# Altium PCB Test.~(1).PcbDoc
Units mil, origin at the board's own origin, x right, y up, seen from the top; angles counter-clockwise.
Board outline 510.01 x 690.03 mil, 2 copper layers (Top Layer, Bottom Layer), stack 62 mil thick; 55 components, 19 nets, 99 pads, 0 vias.
Unrouted connection lines stored in the file: 68.
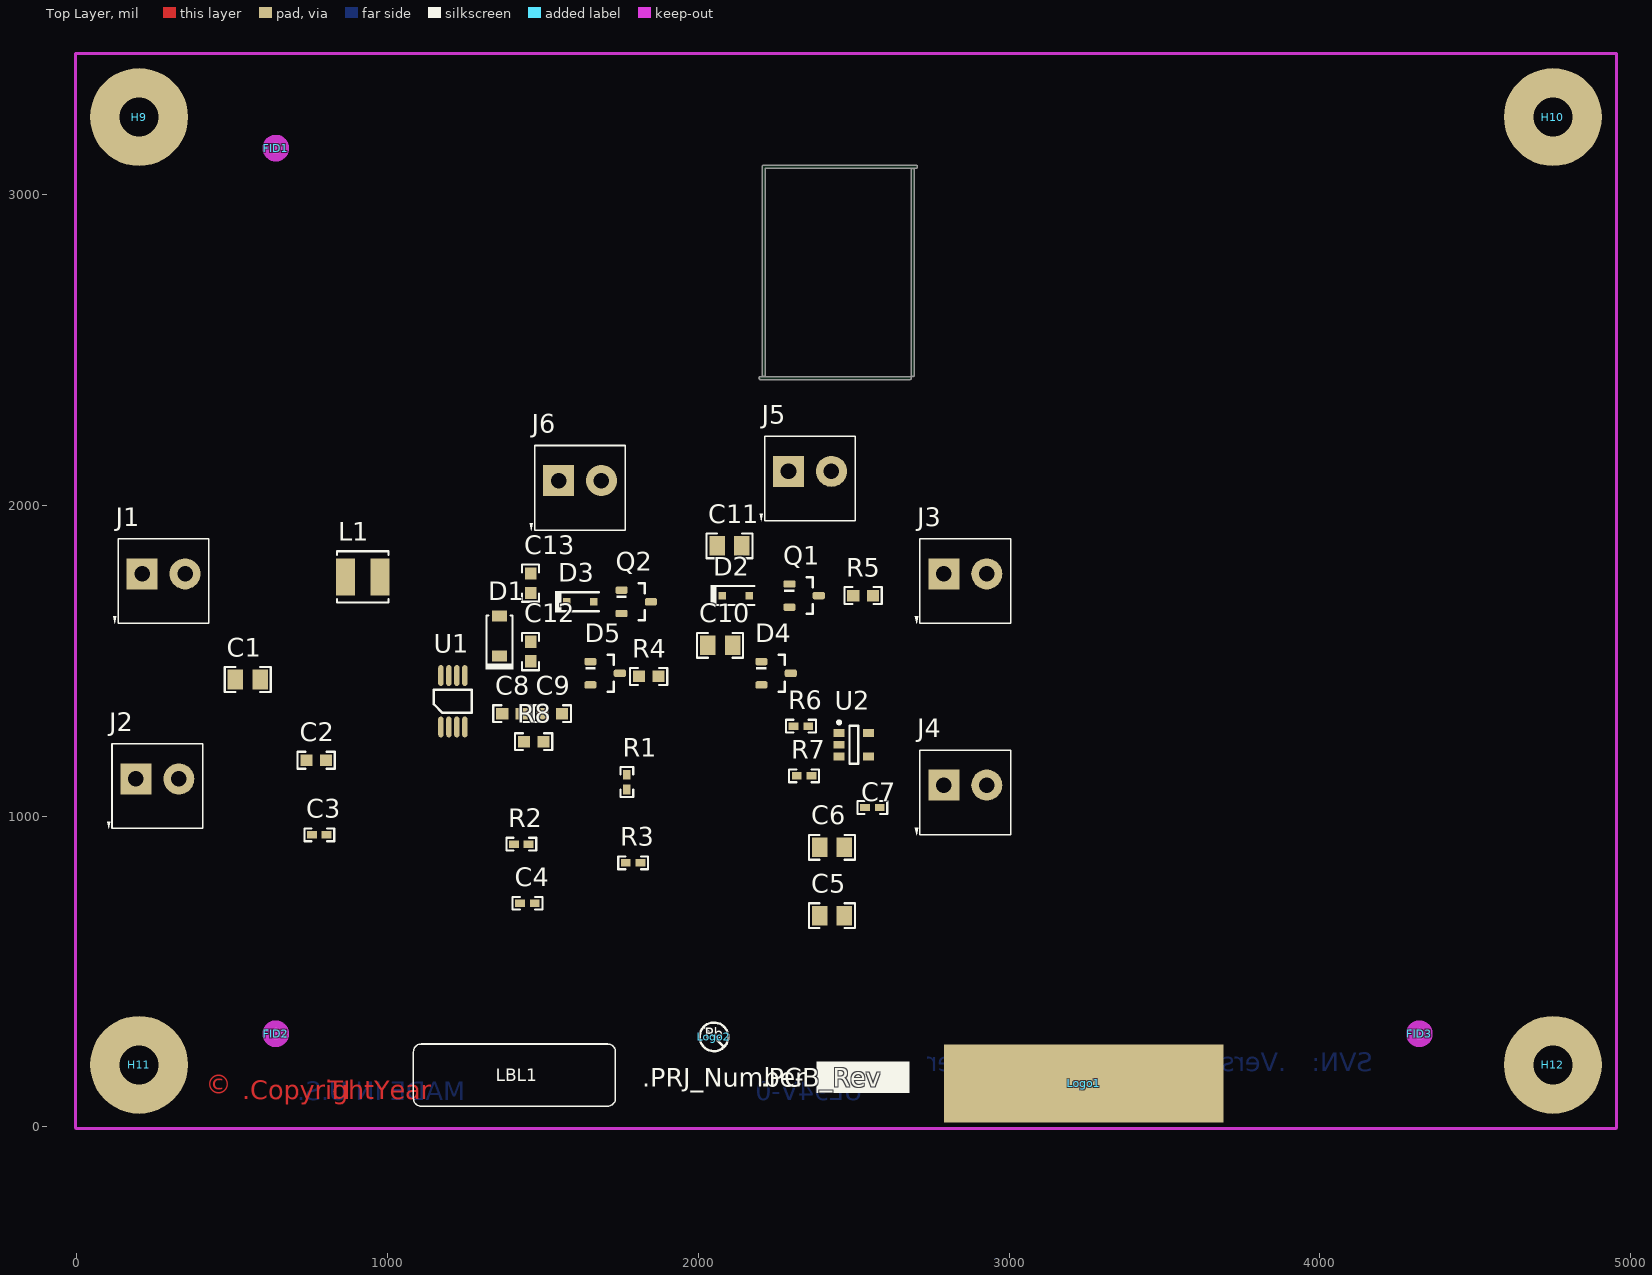
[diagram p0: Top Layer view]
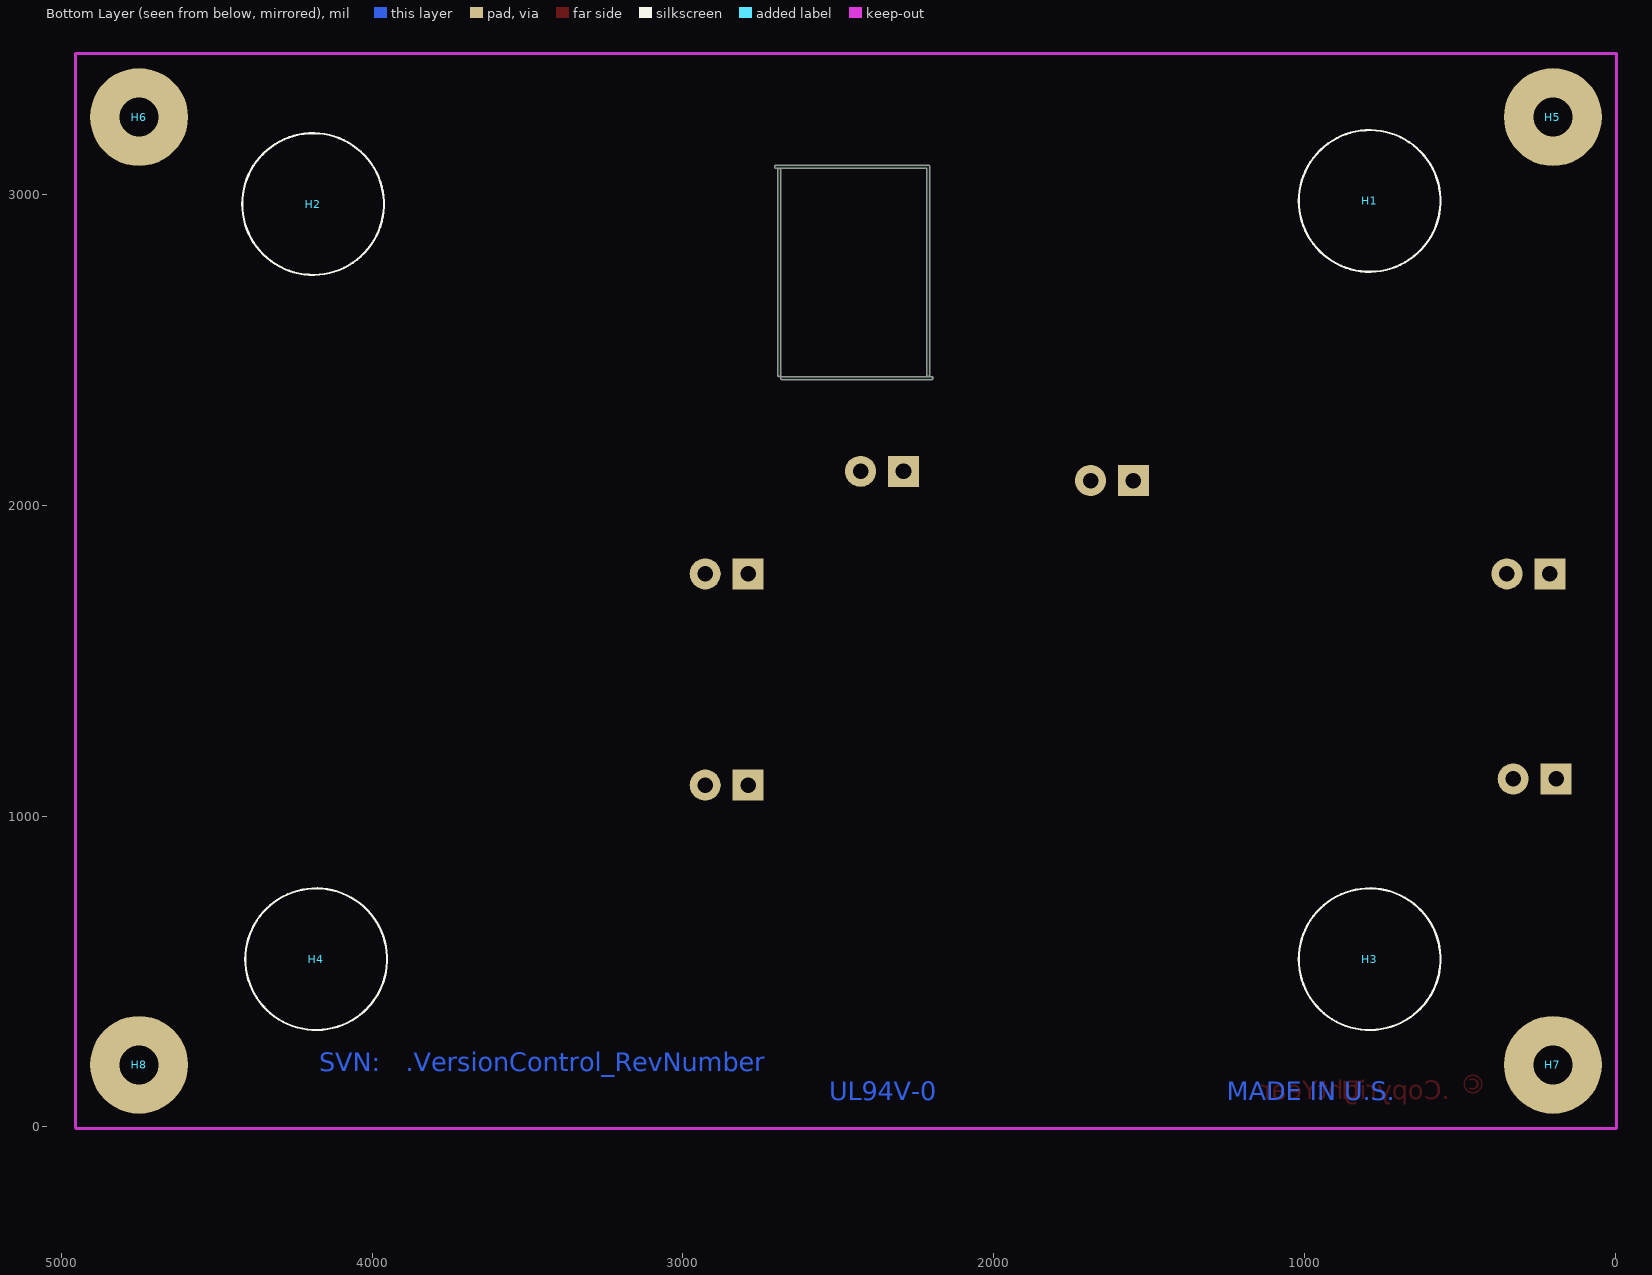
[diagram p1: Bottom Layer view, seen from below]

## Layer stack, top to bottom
Top Solder: solder mask 0.4, Solder Resist, Dk 3.5
Top Layer: signal copper 1.4
Dielectric1: core 59.2, FR-4, Dk 4.8
Bottom Layer: signal copper 1.4
Bottom Solder: solder mask 0.4, Solder Resist, Dk 3.5

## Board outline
2200,2404.99 cw(c2200,2410) 2200,2415.01 2209.45,2415.01 cw(c2210,2420) 2204.99,2420 2204.99,3090 cw(c2210,3090) 2210,3095.02 2700,3095.02 cw(c2700,3090) 2705.01,3090 cw(c2700,3090) 2700,3084.98 2690.55,3084.98 cw(c2690,3080) 2695.01,3080 2695.01,2420 cw(c2690,2420) 2684.99,2420 2684.99,3080 cw(c2690,3080) 2689.45,3084.98 2215.01,3084.98 2215.01,2420 cw(c2210,2420) 2210.55,2415.01 2680,2415.01 cw(c2680,2410) 2685.01,2410 cw(c2680,2410) 2680,2404.99

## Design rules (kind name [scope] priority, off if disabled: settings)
AcuteAngle [All] p1: minimum=4.50000000000000E+0001 checktracksonly=FALSE
AssemblyTestPointUsage [All] p1: valid=2
Clearance Clearance_Keepouts [((IsTrack Or IsArc) And Not InPoly) And IsFree and IsKeepOut vs ((IsTrack Or IsArc) And Not InPoly) And IsFree and IsKeepOut] p1: gap=0
Clearance Clearance_BoardEdge_MountingHoles [OnCopper and InComponentClass('Mounting Holes') vs IsKeepOut] p2: gap=40
Clearance Clearance_BoardEdge_Poly [OnCopper and InPoly vs IsKeepOut] p3: gap=25
Clearance Clearance_BoardEdge [OnCopper and Not InComponentClass('Logo') and not InComponentClass('FiducialMark') and not InRegion(1000,500,4000,800) and Not IsKeepout vs IsKeepOut] p4: gap=75
Clearance Clearance_Poly [InPolygon] p5: gap=25
Clearance [All] p6: gap=7.87
ComponentClearance ComponentClearance_MountingHoles_FiducialMarks [InComponentClass('Mounting Holes') vs InComponentClass('FiducialMark')] p1: gap=50 collisioncheckmode=3 verticalgap=10 showdistances=FALSE
ComponentClearance ComponentClearance_Shunt [InComponentClass('Header') vs InComponentClass('Shunt')] p2: gap=0 collisioncheckmode=3 verticalgap=0 showdistances=FALSE
ComponentClearance ComponentClearance_Logo [InComponentClass('Logo')] p3: gap=50 collisioncheckmode=3 verticalgap=10 showdistances=FALSE
ComponentClearance ComponentClearance_ScrewToNut [(HasFootprint('NY PMS 440 0025 PH')) vs (HasFootprint('Keystone_1902C'))] p4: gap=5 collisioncheckmode=3 verticalgap=10 showdistances=FALSE
ComponentClearance ComponentClearance_MountingHoles [InComponentClass('Mounting Holes')] p5: gap=250 collisioncheckmode=3 verticalgap=100000 showdistances=FALSE
ComponentClearance ComponentClearance_SmallPassives [HasFootprint('0201*') or HasFootprint('0402*') or HasFootprint('0508') or HasFootprint('0603*') or HasFootprint('0612') or HasFootprint('0805*') or HasFootprint('0815*') or HasFootprint('0830*') or HasFootprint('1206*') or HasFootprint('1210*') or HasFootprint('1808*') or HasFootprint('1812*') or HasFootprint('1825*') or HasFootprint('2010*') or HasFootprint('2220*') or HasFootprint('2225*') or HasFootprint('2512*') or HasFootprint('2728*') or HasFootprint('3518*') vs HasFootprint('0201*') or HasFootprint('0402*') or HasFootprint('0508') or HasFootprint('0603*') or HasFootprint('0612') or HasFootprint('0805*') or HasFootprint('0815*') or HasFootprint('0830*') or HasFootprint('1206*') or HasFootprint('1210*') or HasFootprint('1808*') or HasFootprint('1812*') or HasFootprint('1825*') or HasFootprint('2010*') or HasFootprint('2220*') or HasFootprint('2225*') or HasFootprint('2512*') or HasFootprint('2728*') or HasFootprint('3518*')] p6: gap=20 collisioncheckmode=3 verticalgap=10 showdistances=FALSE
ComponentClearance ComponentClearance_THtoSMT [IsThruComponent vs IsSMTComponent] p7: gap=100 collisioncheckmode=3 verticalgap=30 showdistances=FALSE
ComponentClearance ComponentClearance_THtoTH [IsThruComponent vs IsThruComponent] p8: gap=118.11 collisioncheckmode=3 verticalgap=30 showdistances=FALSE
ComponentClearance [All] p9: gap=40 collisioncheckmode=3 verticalgap=10 showdistances=FALSE
DiffPairsRouting [All] p1: maxlimit=100 minlimit=10 mostfreqgap=10 toplayer_minwidth=15 toplayer_maxwidth=15 toplayer_prefwidth=15 bottomlayer_minwidth=15 bottomlayer_maxwidth=15 bottomlayer_prefwidth=15 maxuncoupledlength=1000
FabricationTestPointUsage TestPointUsage [All] p1: valid=2 allowmultiple=FALSE
FabricationTestpoint Testpoint [All] p1: side=3 testpointundercomponent=TRUE minsize=40 maxsize=100 preferedsize=60 minholesize=0 maxholesize=40 preferedholesize=32 testpointgrid=1 allowsidetop=TRUE allowsidebottom=TRUE usegrid=TRUE gridtolerance=0.01
FanoutControl Fanout_LCC [IsLCC] p1: bgadir=Out bgaviamode=Centered fanoutstyle=Auto fanoutdirection=Alternating viagrid=1 // Fanout_LCC (Default Rule)
FanoutControl Fanout_BGA [IsBGA] p2: bgadir=Out bgaviamode=Centered fanoutstyle=Auto fanoutdirection=Alternating viagrid=1 // Fanout_BGA (Default Rule)
FanoutControl Fanout_Default [All] p4: bgadir=Out bgaviamode=Centered fanoutstyle=Auto fanoutdirection=Alternating viagrid=1 // Fanout_Default (Default Rule)
FanoutControl Fanout_Small [(CompPinCount < 5)] p5: bgadir=Out bgaviamode=Centered fanoutstyle=Auto fanoutdirection=OutThenIn viagrid=1 // Fanout_Small (Default Rule)
HoleSize [All] p1: absolutevalues=TRUE maxlimit=251 minlimit=8 maxpercent=80.000 minpercent=20.000
MinimumAnnularRing MinimumAnnularRing_ThermalPadVias [IsVia and InAnyComponent] p1: minimumring=5.91
MinimumAnnularRing [All] p2: minimumring=9
MinimumSolderMaskSliver MinimumSolderMaskSliver_Logo [InComponentClass('Logo') vs InComponentClass('Logo')] p1: minsoldermaskwidth=0.7
MinimumSolderMaskSliver [All] p2: minsoldermaskwidth=3.94
PlaneConnect [All] p1: planeconnectstyle=Relief reliefexpansion=10 reliefentries=4 reliefconductorwidth=10 reliefairgap=10
PolygonConnect [All] p1: connectstyle=Relief reliefconductorwidth=10 reliefentries=4 polygonreliefangle="90 Angle" airgapwidth=10
RoutingVias ThermalPadVias [IsVia and InAnyComponent] p1: holewidth=7.87 width=19.68 viastyle="Through Hole" minholewidth=7.87 minwidth=19.68 maxholewidth=12.99 maxwidth=23.62
RoutingVias [All] p2: holewidth=16 width=34 viastyle="Through Hole" minholewidth=7.87 minwidth=26 maxholewidth=40 maxwidth=65
SilkToBoardRegionClearance [Not ((IsComment or IsDesignator) And (Hide <> 'False')) and not InRegion(1000,500,4000,800)] p1:
SilkToSilkClearance SilkToSilkClearance_Pb-FreeLogo [(HasFootprint('Pb-Free_Overlay_Medium') OR HasFootprint('Pb-Free_Overlay_Small')) vs (HasFootprint('Pb-Free_Overlay_Medium') OR HasFootprint('Pb-Free_Overlay_Small'))] p1: silktosilkclearance=0
SilkToSilkClearance [All] p2: silktosilkclearance=5
SilkToSolderMaskClearance "Silk to Solder Mask Opening" [All] p1: minsilkscreentomaskgap=1 clearancetoexposedcopper=FALSE
SolderMaskExpansion [All] p1: expansion=1.97
UnpouredPolygon [All] p1: allowunpoured=FALSE
Width [All] p1: maxlimit=100 minlimit=6 preferedwidth=10 checkconnectedcopper=TRUE
14 further rules are at their usual default settings.

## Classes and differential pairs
component class Label: LBL1
component class FiducialMark: FID1 FID2 FID3
component class "TPS61085 reference board_Hardware": FID1 FID2 FID3 H1 H2 H3 H4 H5 H6 H7 H8 H9 H10 H11 H12 LBL1 Logo1 Logo2
component class Logo: Logo1
component class "Mounting Holes": H1 H4 H10 H11
component class "TPS61085 reference board": C1 C2 C3 C4 C5 C6 C7 C8 C9 C10 C11 C12 C13 D1 D2 D3 D4 D5 J1 J2 J3 J4 J5 J6 L1 Q1 Q2 R1 R2 R3 R4 R5 R6 R7 R8 U1 U2

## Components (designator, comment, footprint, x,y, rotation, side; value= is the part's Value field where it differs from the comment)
C1 "GRM219R61A106KE44D" 0805_HV 550,1440 r0 top
C2 "GRM185R61C105KE44D" 0603 770,1180 r0 top
C3 "GRM155R71C104KA88D" 0402 780,940 r0 top
C4 "GRM155R61C222KA01D" 0402 1450,720 r0 top
C5 "C2012X5R1E106K125AB" 0805_HV 2430,680 r0 top
C6 "C2012X5R1E106K125AB" 0805_HV 2430,900 r0 top
C7 "GRM155R71C104KA88D" 0402 2560,1028.19 r0 top
C8 "06035C104KAT2A" 0603 1400,1330 r0 top
C9 "06035C104KAT2A" 0603 1530,1330 r0 top
C10 "C2012X7R1H105K125AB" 0805_HV 2070,1550 r0 top
C11 "C2012X7R1H105K125AB" 0805_HV 2100,1870 r0 top
C12 "GRM185R61C105KE44D" 0603 1460,1530 r90 top
C13 "GRM185R61C105KE44D" 0603 1460,1750 r90 top
D1 "MBR120LSFT1G" SOD-123FL 1360,1580 r90 top
D2 "MMSZ5248BS-7-F" sod-323 2120,1710 r0 top
D3 "MMSZ5236BS-7-F" sod-323 1620,1690 r0 top
D4 "BAT54SLT1G" SOT-23 2250,1460 r0 top
D5 "BAT54SLT1G" SOT-23 1700,1460 r0 top
FID1 "Fiducial" Fiducial10-20 640,3150 r0 top
FID2 "Fiducial" Fiducial10-20 640,300 r0 top
FID3 "Fiducial" Fiducial10-20 4320,300 r0 top
H1 "SJ-5303 (CLEAR)" Bumpon_SJ5003Transparent 790,2980 r180 bottom
H2 "SJ-5303 (CLEAR)" Bumpon_SJ5003Transparent 4190,2970 r180 bottom
H3 "SJ-5303 (CLEAR)" Bumpon_SJ5003Transparent 790,540 r180 bottom
H4 "SJ-5303 (CLEAR)" Bumpon_SJ5003Transparent 4180,540 r180 bottom
H5 "1902C" Keystone_1902C 200,3250 r180 bottom locked
H6 "1902C" Keystone_1902C 4750,3250 r180 bottom locked
H7 "1902C" Keystone_1902C 200,200 r180 bottom locked
H8 "1902C" Keystone_1902C 4750,200 r180 bottom locked
H9 "NY PMS 440 0025 PH" "NY PMS 440 0025 PH" 200,3250 r0 top locked
H10 "NY PMS 440 0025 PH" "NY PMS 440 0025 PH" 4750,3250 r0 top locked
H11 "NY PMS 440 0025 PH" "NY PMS 440 0025 PH" 200,200 r0 top locked
H12 "NY PMS 440 0025 PH" "NY PMS 440 0025 PH" 4750,200 r0 top locked
J1 "ED555/2DS" TERM_BLK_ED555-2DS 210,1780 r0 top
J2 "ED555/2DS" TERM_BLK_ED555-2DS 190,1120 r0 top
J3 "ED555/2DS" TERM_BLK_ED555-2DS 2790,1780 r0 top
J4 "ED555/2DS" TERM_BLK_ED555-2DS 2790,1100 r0 top
J5 "ED555/2DS" TERM_BLK_ED555-2DS 2290,2110 r0 top
J6 "ED555/2DS" TERM_BLK_ED555-2DS 1550,2080 r0 top
L1 "LQH44PN3R3MP0L" IND_LQH44P 920,1770 r0 top
LBL1 "Size: 0.65\" x 0.20 \"" Label_650x200 1408,167 r0 top
Logo1 "Texas Instruments" TI_Stacked_SolderMask_Small 3240,140 r0 top
Logo2 "Pb-Free Symbol" Pb-Free_Overlay_Small 2050,290 r0 top
Q1 "BC850CLT1G" SOT-23 2340,1710 r0 top
Q2 "BC857C-7-F" SOT-23 1800,1690 r0 top
R1 "CRCW040216K0JNED" 0402 1770,1110 r90 top
R2 "CRCW040227K0JNED" 0402 1430,910 r0 top
R3 "CRCW0402113KFKED" 0402 1790,850 r0 top
R4 "CPF0603B2K0E" 0603 1840,1450 r0 top
R5 "CPF0603B2K0E" 0603 2530,1710 r0 top
R6 "CRCW040227K0JNED" 0402 2330,1290 r0 top
R7 "CRCW040227K0JNED" 0402 2340,1130 r0 top
R8 "CRCW060310R0FKEA" 0603 1470,1240 r0 top
U1 "TPS61085DGKR" DGK0008A_N 1210,1370 r90 top
U2 "LM7321MF" MF05A_L 2500,1230 r0 top

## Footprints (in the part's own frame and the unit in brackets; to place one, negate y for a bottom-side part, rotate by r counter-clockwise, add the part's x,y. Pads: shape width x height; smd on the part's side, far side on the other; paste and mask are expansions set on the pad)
0402 [mm] "0402 from SM-752 data"
  rect 0.8x0.6 smd: 1(-0.6,0) 2(0.6,0)
  silkscreen extent -1.22,-0.52 1.22,0.52, body extent -0.55,-0.3 0.55,0.3, height 0.6
0603 [mm] "0603 from SM-752 data"
  rect 1x0.95 smd: 1(-0.8,0) 2(0.8,0)
  silkscreen extent -1.52,-0.69 1.52,0.69, body extent -0.87,-0.47 0.87,0.47, height 0.85
0805_HV [mil] "0805 with 30mil clearance between pads"
  rect 50x63 smd: 1(-40,0) 2(40,0)
  silkscreen extent -74,-40 74,40, body extent -43,-29 43,29, height 43
Bumpon_SJ5003Transparent [mil] "3M Hemispherical Bumpon transparent"
  round 1 on Mech4: 0(0,0)
  silkscreen extent -228,-228 228,228, body extent -217,-218 219,218, height 197
DGK0008A_N [mm] "TSOP, 8-Leads, Body 3x3mm, Pitch 0.65mm, IPC Medium Density"
  oval 1.7x0.45 smd mask+0.05: 1(-2.1,0.975) 2(-2.1,0.325) 3(-2.1,-0.325) 4(-2.1,-0.975) 5(2.1,-0.975) 6(2.1,-0.325) 7(2.1,0.325) 8(2.1,0.975)
  silkscreen extent -0.95,-1.55 0.95,1.55, body extent -2.45,-1.5 2.45,1.5, height 0.94
Fiducial10-20 [mm]
  round 1 smd mask+0.5: 1(0,0)
  Top Layer keep-out circle w1.178: c0,0 r0.5
IND_LQH44P [mm] "Murata"
  rect 1.55x3 smd: 1(-1.425,0) 2(1.425,0)
  silkscreen extent -2.1,-2.1 2.1,2.1, body extent -2.1,-2.1 2.1,2.1, height 1.8
Keystone_1902C [mil] "Hex Standoff, 4-40 threaded, nylon"
  body extent -145,-126 146,126, height 501
Label_650x200 [mil] "Thermal Transfer Label"
  silkscreen extent -325,-100 325,100, body extent -326,-101 326,101, height 1
MF05A_L [mm] "SOT23, 5-Leads, Body 2.9x1.6mm, Pitch 0.95mm, Lead Span 2.8mm, IPC High Density"
  rect 0.9x0.65 smd: 1(-1.2,0.95) 2(-1.2,0) 3(-1.2,-0.95) 4(1.2,-0.95) 5(1.2,0.95)
  silkscreen extent -1.32,-1.55 0.35,1.95, body extent -0.9,-1.55 0.9,1.55, height 1.19
"NY PMS 440 0025 PH" [mm] "4-40 nylon screw and mounting hole"
  round 8 hole 3.2: 1(0,0)
  body extent -3.3,-3.3 3.3,3.3, height 2.69
Pb-Free_Overlay_Small [mil]
  silkscreen extent -46,-46 46,46
SOD-123FL [mm] "Copied from SOD-123"
  rect 0.915x1.22 smd: 1(-1.637,0) 2(1.637,0)
  silkscreen extent -2.74,-1.16 1.68,1.16, body extent -1.9,-0.9 1.9,0.9, height 1
sod-323 [mm] "NXP recommended land pattern"
  rect 0.6x0.6 smd paste-0.05: 1(-1.1,0) 2(1.1,0)
  silkscreen extent -2.06,-0.86 1.53,0.86, body extent -1.3,-0.67 1.3,0.68, height 1.1
SOT-23 [mm] "SOT23, 3-Leads, Body 2.9x1.3mm, Pitch 0.95mm, Lead Span 2.5mm, IPC Medium Density"
  rrect50% 1x0.6 smd: 1(-1.2,0.95) 2(-1.2,-0.95) 3(1.2,0)
  silkscreen extent -1.63,-1.5 0.7,1.5, body extent -1.16,-1.45 1.21,1.45, height 1
TERM_BLK_ED555-2DS [mil]
  rect 100x100 hole 50: 1(0,0)
  round 100 hole 50: 2(138,0)
  silkscreen extent -93,-161 215,113, body extent -69,-150 207,106, height 323
TI_Stacked_SolderMask_Small [mil]
  rect 900x250 smd paste-125 mask-125: 0(0,0)

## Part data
C1: "CAP, CERM, 10 μF, 10 V, +/- 10%, X5R, 0805"
C2 C12 C13: "CAP, CERM, 1 μF, 16 V, +/- 10%, X5R, 0603"
C3 C7: "CAP, CERM, 0.1 μF, 16 V, +/- 10%, X7R, 0402"
C4: "CAP, CERM, 2200 pF, 16 V, +/- 10%, X5R, 0402"
C5 C6: "CAP, CERM, 10 μF, 25 V, +/- 10%, X5R, 0805"
C8 C9: "CAP, CERM, 0.1 μF, 50 V, +/- 10%, X7R, 0603"
C10 C11: "CAP, CERM, 1 μF, 50 V, +/- 10%, X7R, 0805"
D1: "Diode, Schottky, 20 V, 1 A, SOD-123FL"
D2: "Diode, Zener, 18 V, 200 mW, SOD-323"
D3: "Diode, Zener, 7.5 V, 200 mW, SOD-323"
D4 D5: "Diode, Schottky, 30 V, 0.2 A, SOT-23"
FID1 FID2 FID3: "Fiducial mark.  There is nothing to buy or mount."
H1 H2 H3 H4: "Bumpon, Hemisphere, 0.44 X 0.20, Clear"
H5 H6 H7 H8: "Standoff, Hex, 0.5\"L #4-40 Nylon"
H9 H10 H11 H12: "Machine Screw, Round, #4-40 x 1/4, Nylon, Philips panhead"
J1 J2 J3 J4 J5 J6: "Terminal Block, 6A, 3.5mm Pitch, 2-Pos, TH"
L1: "Inductor, Shielded Drum Core, Ferrite, 3.3 μH, 1.77 A, 0.065 ohm, SMD"
LBL1: library part THT-14-423-10, "Thermal Transfer Printable Labels, 0.650\" W x 0.200\" H - 10,000 per roll"
Logo1: library part TI_Logo, "Texas Instrument Corporate Signature"
Logo2: library part Pb-Free
Q1: library part "BC850CLT1G, ON Semiconductor", "Transistor, NPN, 45 V, 0.1 A, SOT-23"
Q2: library part "BC857C-7-F, Diodes Inc.", "Transistor, PNP, 45 V, 0.1 A, SOT-23"
R1: "RES, 16 k, 5%, 0.063 W, 0402"
R2 R6 R7: "RES, 27 k, 5%, 0.063 W, 0402"
R3: "RES, 113 k, 1%, 0.063 W, 0402"
R4 R5: "RES, 2.00 k, 0.1%, 0.063 W, 0603"
R8: "RES, 10.0, 1%, 0.1 W, 0603"
U1: "18.5 V, 2 A, 650 KHz / 1.2 MHz Step-Up DC-DC Converter with Forced PWM Mode, 2.3 to 6 V, -40 to 85 degC, 8-pin SOP (DGK8), Green (RoHS & no Sb/Br)"
U2: "Single 30V High Output Current and Unlimited Capacitive Load Op Amp"

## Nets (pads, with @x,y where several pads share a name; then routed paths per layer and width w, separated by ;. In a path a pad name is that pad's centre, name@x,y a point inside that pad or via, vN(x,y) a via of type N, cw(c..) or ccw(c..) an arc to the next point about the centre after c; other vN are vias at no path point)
NetC1_1: C1.1 C2.1 J1.1 J1.2 L1.1 U1.3 U1.6 U1.7
NetC3_1: C3.1 U1.8
NetC4_1: C4.1 R2.1
NetC5_1: C5.1 C6.1 D1.1 D4.1 J3.1 R3.2 R7.2 U2.2
NetC7_1: C7.1 J4.1 U2.1 U2.4
NetC8_1: C8.1 C9.2 R8.2
NetC8_2: C8.2 D5.3
NetC9_1: C9.1 D4.3
NetC10_1: C10.1 D4.2 Q1.3 R5.2
NetC11_1: C11.1 J5.1 Q1.2
NetC12_1: C12.1 D5.1 Q2.3 R4.2
NetC13_1: C13.1 J6.1 Q2.2
NetD1_2: D1.2 L1.2 R8.1 U1.5
NetD2_1: D2.1 Q1.1 R5.1
NetD3_2: D3.2 Q2.1 R4.1
NetR1_2: R1.2 R3.1 U1.2
NetR2_2: R2.2 U1.1
NetR6_2: R6.2 R7.1 U2.3
PGND: C1.2 C2.2 C3.2 C4.2 C5.2 C6.2 C7.2 C10.2 C11.2 C12.2 C13.2 D2.2 D3.1 D5.2 J2.1 J2.2 J3.2 J4.2 J5.2 J6.2 R1.1 R6.1 U1.4 U2.5
pads on no net: FID1.1 FID2.1 FID3.1 H1.0 H2.0 H3.0 H4.0 H9.1 H10.1 H11.1 H12.1 Logo1.0

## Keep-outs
Keep-Out Layer:
  lines w10: -5,0 ccw(c0,0) 0,-5 ; -5,0 ccw(c0,0) 0,-5 ; -5,0 -5,3450 ; -5,3450 cw(c0,3450) 0,3455 ; -5,3450 cw(c0,3450) 0,3455 ; 0,-5 4950,-5 ; 0,3455 4950,3455 ; 4950,-5 ccw(c4950,0) 4955,0 ; 4950,-5 ccw(c4950,0) 4955,0 ; 4950,3455 cw(c4950,3450) 4955,3450 ; 4950,3455 cw(c4950,3450) 4955,3450 ; 4955,0 4955,3450
  text ".Layer_Name" at 577,-858.49 h60

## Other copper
Top Layer:
  text ".CopyrightYear" at 532,90 h60
  text "TI" at 808,90 h60
  text "©" at 415,86.48 h105
  text ".Layer_Name" at 577,-858.49 h60
Bottom Layer:
  text ".VersionControl_RevNumber" at 3891,179.5 h60
  text "SVN:" at 4170,179.5 h60
  text "MADE IN U.S." at 1250,86.5 h60
  text "UL94V-0" at 2529.5,86.5 h60
  text ".Layer_Name" at 577,-858.49 h60

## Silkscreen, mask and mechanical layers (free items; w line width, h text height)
Top Overlay:
  region: 2680,210 2380,210 2380,110 2680,110
  text ".PRJ_Number" at 1820,130.01 h60
  text ".PCB_Rev" at 2200,130.01 h60
  text "-" at 2310,130.01 h60
  text ".Layer_Name" at 577,-858.49 h60
Bottom Overlay:
  text ".Layer_Name" at 577,-858.49 h60
Top Paste:
  text ".Layer_Name" at 577,-858.49 h60
Bottom Paste:
  text ".Layer_Name" at 577,-858.49 h60
Top Solder:
  text ".Layer_Name" at 577,-858.49 h60
  text ".Layer_Name" at 577,-858.49 h60
Bottom Solder:
  text ".Layer_Name" at 577,-858.49 h60
Drill Guide:
  text ".Layer_Name" at 577,-858.49 h60
M1 Board Outline:
  lines w10: 0,0 4950,0 4950,3450 0,3450 0,0 ; 2200,2410 2210,2420 2210,3090 2700,3090 2690,3080 2690,2420 2680,2410 2200,2410
  text ".Layer_Name" at 577,-858.49 h60
M2 Board Dimensions:
  rectangle: 125,-400 500,-275
  rectangle: 0,-275 125,-150
  lines w7: 0,-275 1000,-275 ; 125,-400 125,-150 ; 250,-400 250,-150 ; 500,-400 500,-150 ; 750,-400 750,-150 ; 0,-400 0,-150 1000,-150 1000,-400 0,-400
  text ".Layer_Name" at 577,-858.49 h60
M3 3D STEP Top:
  text ".Layer_Name" at 577,-858.49 h60
M4 3D STEP Bottom:
  text ".Layer_Name" at 577,-858.49 h60
M5 Assembly Top:
  lines w10: -292,-930.17 6308,-930.17 ; -292,-726.83 6310,-726.83 ; -292,-523.5 -292,-1133.5 3713,-1133.5 6310,-1133.5 6310,-523.5 -291.5,-523.5 -291.5,-1133.5 1284,-1133.5 ; 2173,-1133.5 2173,-523.5 ; 3440,-726.83 3440,-523.5 ; 4280,-726.83 4280,-523.5 ; 4902,-1140 4902,-937.17
  text "COMPONENTS MARKED 'DNP' SHOULD NOT BE POPULATED." at 1153.5,-318.5 h60
  text "ASSEMBLY VARIANT:" at 1153,-434 h60
  text ".VariantName" at 2189,-434 h60
  text "PCB VIEWED FROM TOP SIDE" at -228.5,-655.67 h60
  text "BOARD #:" at 2248,-655.67 h60
  text ".PRJ_Number" at 2793.5,-655.67 h60
  text "REV:" at 3638,-655.67 h60
  text ".PCB_Rev" at 3929.5,-655.67 h60
  text "SVN REV:" at 4476,-655.67 h60
  text ".VersionControl_RevNumber" at 4982,-655.67 h60
  text "PLOT NAME =" at -228.5,-1064.34 h60
  text ".plot_File_Name" at 577,-1064.34 h60
  text "GENERATED    :" at 2250,-1064.34 h60
  text ".Print_Date" at 3119.5,-1064.34 h60
  text ".Print_Time" at 3848.5,-1064.34 h60
  text "TEXAS INSTRUMENTS" at 5113,-1064.34 h60
M6 Assembly Bottom:
  lines w10: -292.5,-727.33 6309.5,-727.33 ; -290.5,-930.67 6309.5,-930.67 ; 1115.5,-1140.5 1115.5,-937.67 ; 1737.5,-727.33 1737.5,-524 ; 2577.5,-727.33 2577.5,-524 ; 3844.5,-1134 3844.5,-524 ; 4733.5,-1134 6309,-1134 6309,-524 -292.5,-524 -292.5,-1134 2304.5,-1134 6309.5,-1134 6309.5,-524
  text "COMPONENTS MARKED 'DNP' SHOULD NOT BE POPULATED." at 6102,-318 h60
  text ".VariantName" at 5058,-434 h60
  text "ASSEMBLY VARIANT:" at 6097,-434 h60
  text ".VersionControl_RevNumber" at 1035.5,-656.17 h60
  text "SVN REV:" at 1541.5,-656.17 h60
  text ".PCB_Rev" at 2088,-656.17 h60
  text "REV:" at 2379.5,-656.17 h60
  text ".PRJ_Number" at 3224,-656.17 h60
  text "BOARD #:" at 3769.5,-656.17 h60
  text "PCB VIEWED FROM BOTTOM SIDE" at 6246,-656.17 h60
  text "TEXAS INSTRUMENTS" at 904.5,-1064.84 h60
  text ".Print_Time" at 2169,-1064.84 h60
  text ".Print_Date" at 2898,-1064.84 h60
  text "GENERATED    :" at 3767.5,-1064.84 h60
  text ".plot_File_Name" at 5440.5,-1064.84 h60
  text "PLOT NAME =" at 6246,-1064.84 h60
M9 Title Sheet:
  drawing of 57 lines, arcs and shapes, not listed
  text "1" at 739.84,8036.5 h70
  text "2" at 3235.5,8036.5 h70
  text "3" at 5724.84,8036.5 h70
  text "4" at 8231.51,8036.5 h70
  text "5" at 10730.5,8036.5 h70
  text "6" at 13235.5,8036.5 h70
  text "A" at -416.5,6893.5 h70
  text "A" at 14383.5,6893.5 h70
  text "B" at -416.5,4513.5 h70
  text "B" at 14383.5,4513.5 h70
  text "C" at -416.5,2138.5 h70
  text "C" at 14383.5,2138.5 h70
  text "PROJECT TITLE:" at 11343.5,277.5 h45
  text ".PRJ_Title" at 11393.5,144.17 h70
  text "DESIGNED FOR:" at 11343.5,-23.5 h45
  text ".PRJ_Customer" at 11393.5,-163.5 h70
  text "D" at -416.5,-231.5 h70
  text "D" at 14383.5,-231.5 h70
  text "FILE NAME:" at 11343.5,-323.5 h45
  text ".PCB_File_Name_No_Path" at 11393.5,-443.5 h70
  text "Texas Instruments (TI) and/or its licensors do not warrant the accuracy or completeness of this specification" at 6374,-605.34 h45
  text "ENGINEER:" at 11343.5,-613.5 h45
  text "LAYOUT BY:" at 12848.5,-613.5 h45
  text "or any information contained therein. TI and/or its licensors do not warrant that this design will meet" at 6329.01,-718 h45
  text ".PRJ_Engineer" at 11393.5,-768.49 h70
  text ".PCB_Layout" at 12899,-768.49 h70
  text "the specifications, will be suitable for your application or fit for any particular purpose, or will operate in" at 6329.01,-830.67 h45
  text ".Layer_Name" at 577,-858.49 h60
  text "ALTIUM DESIGNER VERSION:" at 12848.5,-923.5 h45
  text "an implementation. TI and/or its licensors do not warrant that the design is production worthy. You should" at 6329.01,-943.33 h45
  text "completely validate and test your design implementation to confirm the system functionality for your application." at 6374,-1056 h45
  text ".print_Scale" at 11393.5,-1056.83 h70
  text ".Application_BuildNumber" at 12899,-1056.83 h70
  text "1" at 739.84,-1263.5 h70
  text "2" at 3235.5,-1263.5 h70
  text "3" at 5724.84,-1263.5 h70
  text "4" at 8231.51,-1263.5 h70
  text "5" at 10730.5,-1263.5 h70
  text "6" at 13235.5,-1263.5 h70
M10 Fab Notes:
  drawing of 185 lines, arcs and shapes, not listed
  text "DESIGN INFORMATION" at 12381.02,5910 h60
  text "MIN. TRACK WIDTH:" at 11736.46,5730 h60
  text "8" at 12832.7,5730 h60
  text "MIL" at 12987.46,5730 h60
  text "MIN. CLEARANCE:" at 11736.46,5598 h60
  text "0.2" at 12772.7,5598 h60
  text "mm" at 12987.46,5598 h60
  text "MIN. VIA PAD SIZE:" at 11736.46,5466 h60
  text "24" at 12802.71,5466 h60
  text "MIL" at 12987.46,5466 h60
  text "0.05mm (2MIL)" at 12431.46,5324.29 h60
  text "MINIMUM ANNULAR RING" at 11407.23,5320 h60
  text "EXTERNAL" at 13139.46,5320 h60
  text "PER" at 11607.23,5202 h60
  text "IPC-D-275 CLASS 2 LEVEL C" at 11827.23,5202 h60
  text "MIL, HOLES" at 13315.46,5089.71 h60
  text "+/-" at 12923,5089 h60
  text "+/-" at 13777,5089 h60
  text "REGISTRATION TOLERANCES:" at 11407.23,5084 h60
  text "METAL" at 12607,5084 h60
  text "5" at 13183.2,5084 h60
  text "3" at 14016.2,5084 h60
  text "MIL" at 14132.46,5084 h60
  text "MATERIAL:" at 11332.46,4874.54 h60
  text "FR-4 High Tg" at 12318.9,4734.21 h60
  text "FR-408" at 11753.46,4725.64 h60
  text "X" at 12165.46,4725.64 h60
  text "OTHER" at 13241.46,4725.64 h60
  text "62 MIL (1.6mm) +/-10%" at 12073.56,4562.92 h60
  text "THICKNESS:" at 11407.23,4558.64 h60
  text "X" at 11945.4,4558.64 h60
  text "OTHER" at 13358.46,4558.64 h60
  text "TOLERANCE:" at 11407.23,4400.64 h60
  text "X" at 12246.53,4400.64 h60
  text "ANSI IPC-6012 TYPE 3 CLASS 2" at 12433.48,4400.64 h60
  text "OTHER +/-" at 12433.46,4244.64 h60
  text "BOW & TWIST:" at 11407.23,4087.64 h60
  text "X" at 12246.53,4087.64 h60
  text "ANSI IPC-6012 TYPE 3 CLASS 2" at 12433.48,4087.64 h60
  text "OTHER +/-" at 12433.46,3929.13 h60
  text "DRILLING:" at 11332.46,3790.64 h60
  text "REFERENCE:" at 11407.23,3673.64 h60
  text "X" at 12055.46,3673.64 h60
  text "AS SHOWN" at 12242.46,3673.64 h60
  text "X" at 12956.46,3673.64 h60
  text "NC_DRILL FILES" at 13093.46,3673.64 h60
  text "PTH MIN COPPER THICKNESS:" at 11407.23,3515.64 h60
  text "X" at 12757.46,3515.64 h60
  text "1MIL" at 12894.46,3515.64 h60
  text "OTHER" at 13391.46,3515.64 h60
  text "BOARD FINISH:" at 11332.46,3356.64 h60
  text "SILKSCREEN:" at 11487.68,3238.64 h60
  text "X" at 12436.46,3238.64 h60
  text "TOP" at 12562.46,3238.64 h60
  text "X" at 12946.46,3238.64 h60
  text "BOTTOM" at 13073.46,3238.64 h60
  text "SILKSCREEN COLOR:" at 11487.68,3071.64 h60
  text "X" at 12435.42,3071.64 h60
  text "WHITE" at 12562.46,3071.64 h60
  text "OTHER" at 13073.46,3071.64 h60
  text "SOLDER RESIST COLOR:" at 11487.68,2901.64 h60
  text "X" at 12055.42,2742.44 h60
  text "GREEN" at 12182.46,2742.44 h60
  text "BLUE" at 12773.46,2742.44 h60
  text "OTHER" at 13311.46,2742.44 h60
  text "IMMERSION GOLD (ENIG)" at 12393.46,2553.92 h60
  text "ENEPIG" at 13731,2550.64 h60
  text "SURFACE FINISH:" at 11332.46,2549.64 h60
  text "X" at 12206.51,2549.64 h60
  text "IMM. TIN/SILVER OR EQUIV" at 11662,2392.64 h60
  text "OTHER" at 13093.46,2392.64 h60
  text "ARRAY/PANEL:" at 11332.46,2213.64 h60
  text "CUT AND TRIM PER MECH LAYER 1" at 12393.46,2209.35 h60
  text "N.C. ROUTE" at 12393.46,2057.64 h60
  text "X" at 13072.46,2057.64 h60
  text "V. SCORE" at 13259.46,2057.64 h60
  text "CERTIFICATION:" at 11332.46,1920.64 h60
  text "MATERIALS AND WORKMANSHIP FOR ALL PCBS" at 12057.46,1920.64 h60
  text "TO MEET OR EXCEED THE REQUIREMENTS OF:" at 12057.46,1822.64 h60
  text "X" at 11683.96,1686.13 h60
  text "ANSI IPC-A-600F CLASS ->" at 11822.96,1686.13 h60
  text "X" at 13462.02,1686.13 h60
  text "2" at 13580.96,1686.14 h60
  text "1" at 13265.96,1684.64 h60
  text "3" at 13934.96,1684.64 h60
  text "X" at 11686.02,1526.64 h60
  text "UL 94V-0" at 11822.96,1526.64 h60
  text "X" at 12498.02,1526.64 h60
  text "RoHS" at 12634.96,1526.64 h60
  text "OTHER" at 13279.36,1526.64 h60
  text "PER ORDER" at 13676.42,1526.64 h60
  text "ADDITIONAL REQUIREMENTS:" at 11332.46,1385.64 h60
  text "MICROSECTION:" at 11407.23,1270.64 h60
  text "YES" at 12312.96,1270.64 h60
  text "REQUIRED" at 13174.46,1114.49 h60
  text "BARE BOARD ELEC. TEST:" at 11407.23,1111.64 h60
  text "NONE" at 12712.96,1111.64 h60
  text "X" at 13047.46,1111.64 h60
  text "PER ORDER" at 13766.46,1111.64 h60
  text "MANUFACTURER'S UL:" at 11407.23,954.64 h60
  text "RAIL" at 12572.96,950.35 h60
  text "METAL" at 13064.77,950.35 h60
  text "X" at 13440,950 h60
  text "SILK" at 13576.46,950.35 h60
  text ".Layer_Name" at 577,-858.49 h60
M11 Gerber Information:
  lines w10: -292,-930.17 6308,-930.17 ; -292,-726.83 6310,-726.83 ; -292,-523.5 -292,-1133.5 3713,-1133.5 6310,-1133.5 6310,-523.5 -291.5,-523.5 -291.5,-1133.5 1284,-1133.5 ; 2173,-1133.5 2173,-523.5 ; 3440,-726.83 3440,-523.5 ; 4280,-726.83 4280,-523.5 ; 4902,-1140 4902,-937.17
  text "ALL ARTWORK VIEWED FROM TOP SIDE" at -228.5,-655.67 h60
  text "BOARD #:" at 2248,-655.67 h60
  text ".PRJ_Number" at 2793.5,-655.67 h60
  text "REV:" at 3638,-655.67 h60
  text ".PCB_Rev" at 3929.5,-655.67 h60
  text "SVN REV:" at 4476,-655.67 h60
  text ".VersionControl_RevNumber" at 4982,-655.67 h60
  text "LAYER NAME =" at -228.5,-858.49 h60
  text "PLOT NAME =" at -228.5,-1064.34 h60
  text ".plot_File_Name" at 577,-1064.34 h60
  text "GENERATED    :" at 2250,-1064.34 h60
  text ".Print_Date" at 3119.5,-1064.34 h60
  text ".Print_Time" at 3848.5,-1064.34 h60
  text "TEXAS INSTRUMENTS" at 5113,-1064.34 h60
M12 Stackup:
  drawing of 191 lines, arcs and shapes, not listed
  text "Layer" at 9790.34,7830 h60
  text "Name" at 10200.26,7830 h60
  text "Material" at 11130,7830 h60
  text "Thickness" at 11989.77,7830 h60
  text "Constant" at 12639.6,7830 h60
  text "Board Layer Stack" at 13209.46,7830 h60
  text "1" at 9790.34,7710 h60
  text "Top Overlay" at 10200.26,7710 h60
  text "2" at 9790.34,7590 h60
  text "Top Solder" at 10200.26,7590 h60
  text "Solder Resist" at 11130,7590 h60
  text "0.40mil" at 11989.77,7590 h60
  text "3.5" at 12639.6,7590 h60
  text "3" at 9790.34,7470 h60
  text "Top Layer" at 10200.26,7470 h60
  text "Copper" at 11130,7470 h60
  text "1.40mil" at 11989.77,7470 h60
  text "4" at 9790.34,7350 h60
  text "Dielectric1" at 10200.26,7350 h60
  text "FR-4" at 11130,7350 h60
  text "59.20mil" at 11989.77,7350 h60
  text "4.8" at 12639.6,7350 h60
  text "5" at 9790.34,7230 h60
  text "Bottom Layer" at 10200.26,7230 h60
  text "Copper" at 11130,7230 h60
  text "1.40mil" at 11989.77,7230 h60
  text "6" at 9790.34,7110 h60
  text "Bottom Solder" at 10200.26,7110 h60
  text "Solder Resist" at 11130,7110 h60
  text "0.40mil" at 11989.77,7110 h60
  text "3.5" at 12639.6,7110 h60
  text "7" at 9790.34,6990 h60
  text "Bottom Overlay" at 10200.26,6990 h60
  text ".Layer_Name" at 577,-858.49 h60
M13 Component Bodies Top:
  text ".Layer_Name" at 577,-858.49 h60
M14 Component Bodies Bottom:
  text ".Layer_Name" at 577,-858.49 h60
M15 Courtyards Top:
  text ".Layer_Name" at 577,-858.49 h60
M16 Courtyards Bottom:
  text ".Layer_Name" at 577,-858.49 h60
Drill Drawing:
  circle w1: c5692.72,3221.04 r24.89
  lines w1: 5667.83,3046.84 5717.6,3046.84 5717.6,3096.61 5667.83,3096.61 5667.83,3046.84
  lines w12: 5600,3002.04 7718.02,3002.04 ; 5600,3300.68 7718.02,3300.68 ; 5970.36,2852.72 5970.36,3450 ; 6327.36,2852.72 6327.36,3450 ; 6988.93,2852.72 6988.93,3450 ; 7273.07,2852.72 7273.07,3450 ; 5600,2852.72 7718.02,2852.72 7718.02,3450 5600,3450 5600,2852.72
  text "Symbol" at 5689.59,3345.48 h72
  text "Quantity" at 6015.16,3345.48 h72
  text "Finished Hole Size" at 6372.16,3345.48 h72
  text "Plated" at 7033.72,3345.48 h72
  text "Hole Type" at 7317.86,3345.48 h72
  text "12" at 6015.16,3196.16 h60
  text "50.00mil (1.270mm)" at 6372.16,3196.16 h60
  text "PTH" at 7033.72,3196.16 h60
  text "Round" at 7317.86,3196.16 h60
  text "4" at 6015.16,3046.84 h60
  text "125.98mil (3.200mm)" at 6372.16,3046.84 h60
  text "PTH" at 7033.72,3046.84 h60
  text "Round" at 7317.86,3046.84 h60
  text "16 Total" at 6015.16,2897.52 h60
  text ".Layer_Name" at 577,-858.49 h60

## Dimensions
0,0 to 2200,2415.01 on M2 Board Dimensions
0,0 to 2204.99,2420 on M2 Board Dimensions
0,-400 to 1000,-400 on M2 Board Dimensions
